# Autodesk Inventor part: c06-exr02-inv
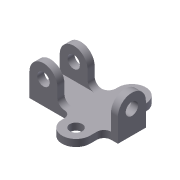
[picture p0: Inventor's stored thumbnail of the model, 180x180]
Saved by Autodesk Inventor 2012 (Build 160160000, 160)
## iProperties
Shininess: 77.0
Length Units: 11269
Angle Units: 11279
Time Units: 11290
Mass Units: 11283
Length Display Precision: 3
Angle Display Precision: 2
Created: 2001-12
Part Number: c06-exr02-inv
Document SubType Name: Modeling
Designer: Renu Muthoo
Density: 1 g/cm^3
Material: Default
Density: 0.0
Volumn: 0.0
Area: 0.0
PropertySet Name: Model Information
Control State: 0
Master: False
Checked Out: False
Author: Renu Muthoo
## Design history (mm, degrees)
sketch "Sketch1"
  geometry: L1 (-67.071, 39)-(-22.071, 39); L2 (-13.071, 48)-(-13.071, 51); L3 (22.929, 51)-(22.929, 42); L4 (31.929, 33)-(31.929, -3); L5 (-67.071, -9)-(-22.071, -9); L6 (-13.071, -18)-(-13.071, -21); L7 (22.929, -21)-(22.929, -12); L8 (-67.071, 39)-(-67.071, -9); L9 (31.929, 33)-(31.929, 33); L10 (31.929, -3)-(31.929, -3); C1 r 8 at (4.929, 51); C2 r 8 at (4.929, -21); A1 r 18 centre (4.929, 51) between (22.929, 51) and (-13.071, 51); A2 r 18 centre (4.929, -21) between (-13.071, -21) and (22.929, -21); A3 r 9 centre (-22.071, 48) between (-22.071, 39) and (-13.071, 48); A4 r 9 centre (-22.071, -18) between (-13.071, -18) and (-22.071, -9); A5 r 9 centre (31.929, -12) between (31.929, -3) and (22.929, -12); A6 r 9 centre (31.929, 42) between (22.929, 42) and (31.929, 33)
  constraints: 20 end point, 12 point on circle, 10 tangent, 8 centre point, 5 equal radius, 3 parallel, 2 coincident, 2 perpendicular, 1 horizontal
  dimensions: "d1" = 18 radius of A1; "d2" = 99 distance between parallel lines of L4 L8; "d4" = 9 radius of A3; "d5" = 9 vertical distance of A6.centre A1.centre; "d6" = 9 vertical distance of A5.centre A2.centre; "d7" = 36 distance of L4.start L4.end; "d8" = 48 distance of L1.start L5.start; "d9" = 6 vertical distance of L4.start L1.start; "d10" = 16 diameter of C1
extrude "Extrusion1" new body sketch "Sketch1" distance "d11" = 9; taper "d12" = 0 deg
sketch "Sketch2"
  geometry: L1 (0, 36)-(0, 0) reference; L2 (0, 0)-(-30, 0); L3 (-30, 36)-(0, 36); C1 r 8 at (-30, 18); A1 r 18 centre (-30, 18) between (-30, 36) and (-30, 0)
  constraints: 4 end point, 2 centre point, 2 point on circle, 2 tangent, 1 coincident, 1 parallel, 1 perpendicular
  dimensions: "d13" = 16 diameter of C1; "d22" = 30 distance of L1.end L2.end
extrude "Extrusion2" join sketch "Sketch2" distance "d14" = 9; taper "d15" = 0 deg
sketch "Sketch3"
  geometry: L1 (0, 9)-(0, 30); L2 (36, 30)-(36, 9); L3 (36, 9)-(0, 9); L4 (45, 9)-(0, 9) reference; C1 r 8 at (18, 30); A1 r 18 centre (18, 30) between (36, 30) and (0, 30)
  constraints: 6 end point, 2 centre point, 2 point on circle, 2 tangent, 1 coincident, 1 collinear, 1 parallel, 1 perpendicular
  dimensions: "d16" = 16 diameter of C1; "d17" = 18 radius of A1; "d18" = 21 distance from line of L4 C1.centre
extrude "Extrusion3" join sketch "Sketch3" distance "d19" = 9; taper "d20" = 0 deg
fillet "Fillet1" dims "d21" = 9
workplane "Work Plane1"
mirror "Mirror1"
body "Solid1"
other parameters: "d23" = -24
